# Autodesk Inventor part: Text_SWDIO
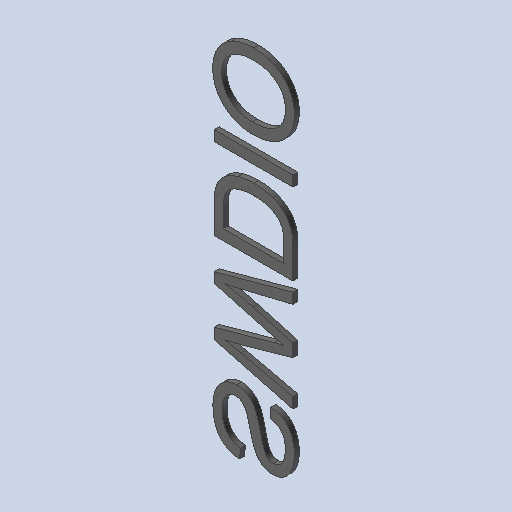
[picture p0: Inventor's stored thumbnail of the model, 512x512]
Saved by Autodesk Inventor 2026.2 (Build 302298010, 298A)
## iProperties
Created: 2026-10
Part Number: Text_SWDIO
Material: Générique
Document SubType Name: Modeling
Designer: mel
Density: 1 g/cm^3
Appearance: Par défaut
Author: mel
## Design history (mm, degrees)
feature "Base1"
feature "Base2"
feature "Base3"
feature "Base4"
feature "Base5"
node "Solide1"
node "Solide2"
node "Solide3"
node "Solide4"
node "Solide5"
